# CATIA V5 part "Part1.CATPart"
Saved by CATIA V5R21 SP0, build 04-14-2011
Part number: Part1
Bounding box of the stored display mesh (mm): x -100 to 100, y -50 to 50, z 0 to 10
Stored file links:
  D:\CATIA V5R21 E-RESOURCES\CATIA-V5R21\catia-v5r21-prt\c16-catia-v5r20-prt\Planer Joint-(Fig16-33)\CAT_V5R21_Part1.CATPart
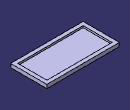
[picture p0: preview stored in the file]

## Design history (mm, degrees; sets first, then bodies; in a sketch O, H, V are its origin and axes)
Body1 (main body)
  Sketch1 on xy-plane, origin (0, 0, 0), H (1, 0, 0), V (0, 1, 0)
    line L1 (100, 50) -> (100, -50)
    line L2 (100, -50) -> (-100, -50)
    line L3 (-100, -50) -> (-100, 50)
    line L4 (-100, 50) -> (100, 50)
    line L5 (90, 40) -> (90, -40)
    line L6 (90, -40) -> (-90, -40)
    line L7 (-90, -40) -> (-90, 40)
    line L8 (-90, 40) -> (90, 40)
    length L4 = 200
    length L1 = 100
    length L8 = 180
    length L5 = 80
    vertical: L1 V, L3 V, L5 V, L7 V
    horizontal: L2 H, L4 H, L6 H, L8 H
    equidistance: L1 L3 O, L2 L4 O, L5 L7 O, L6 L8 O
  MultiPad1: profile Sketch1, domains (length 5; length 10)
